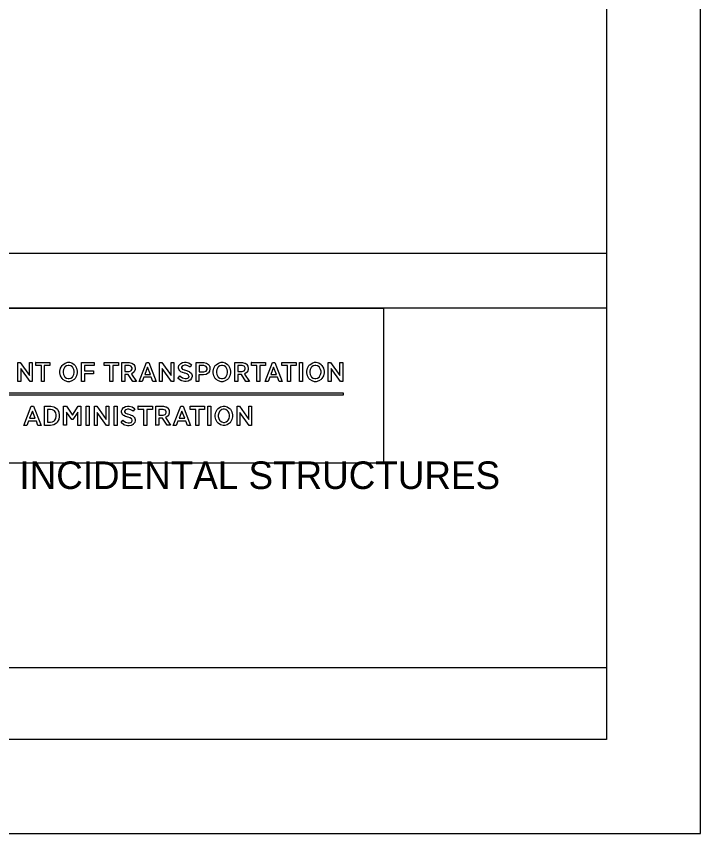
# Model space of a CAD drawing. Extents: x -0.5 to 19.9, y 5.2 to 17.3.
# Drawn here: x 17.634 to 19.938, y 5.667 to 8.417 of the extents above; entities that cross this region are included whole.
import ezdxf

# ---------------------------------------------------------------- set-up
doc = ezdxf.new("R2010")
doc.units = 0
for name, color, linetype in [('BORD-LINE', 7, 'Continuous'), ('MSHA-LOGO', 7, 'Continuous'), ('TTLB-TEXT', 7, 'Continuous'), ('USER-CLIP', 7, 'Continuous'), ('USER-LINE', 7, 'Continuous')]:
    doc.layers.add(name, color=color, linetype=linetype)

msp = doc.modelspace()

# ---------------------------------------------------------------- linework, layer by layer
at = {"layer": 'BORD-LINE'}
for p, q in [((19.6208, 7.6193), (12.2466, 7.6193)), ((19.6208, 7.4352), (15.1479, 7.4352)), ((15.1479, 6.2262), (19.6208, 6.2262))]:
    msp.add_line(p, q, dxfattribs=at)
msp.add_lwpolyline([(12.2466, 16.3375), (19.6208, 16.3375), (19.6208, 5.9844), (12.2466, 5.9844)], close=True, dxfattribs=at)
at = {"layer": 'MSHA-LOGO'}
for points in [[(17.6799, 7.189), (17.6485, 7.2324), (17.6485, 7.189), (17.639, 7.189), (17.639, 7.2525), (17.6465, 7.2525), (17.6779, 7.2091), (17.6779, 7.2525), (17.6874, 7.2525), (17.6874, 7.189)], [(17.6989, 7.2528), (17.747, 7.2528), (17.747, 7.2426), (17.728, 7.2426), (17.728, 7.1893), (17.7182, 7.1893), (17.7182, 7.2426), (17.6992, 7.2426), (17.6992, 7.2528)], [(17.7892, 7.2439), (17.7905, 7.2455), (17.7985, 7.251), (17.8069, 7.2535), (17.8098, 7.2535), (17.8126, 7.2535), (17.821, 7.2512), (17.829, 7.2458), (17.8304, 7.2443), (17.8318, 7.2427), (17.8367, 7.2338), (17.8389, 7.2241), (17.8389, 7.2209), (17.8389, 7.2177), (17.8367, 7.2081), (17.8318, 7.1991), (17.8304, 7.1975), (17.829, 7.196), (17.821, 7.1906), (17.8126, 7.1883), (17.8098, 7.1883), (17.8069, 7.1883), (17.7985, 7.1906), (17.7905, 7.196), (17.7892, 7.1975), (17.7878, 7.1991), (17.7828, 7.208), (17.7807, 7.2177), (17.7807, 7.2209), (17.7807, 7.2241), (17.7828, 7.2335), (17.7878, 7.2424)], [(17.7967, 7.2051), (17.7976, 7.204), (17.8028, 7.2004), (17.8083, 7.1989), (17.8101, 7.1989), (17.8119, 7.1989), (17.8174, 7.2004), (17.8226, 7.204), (17.8235, 7.2051), (17.8244, 7.2061), (17.8276, 7.212), (17.8291, 7.2187), (17.8291, 7.2209), (17.8291, 7.2231), (17.8276, 7.2298), (17.8244, 7.2357), (17.8235, 7.2367), (17.8226, 7.2378), (17.8174, 7.2414), (17.8119, 7.2429), (17.8101, 7.2429), (17.8083, 7.2429), (17.8028, 7.2414), (17.7976, 7.2378), (17.7967, 7.2367), (17.7958, 7.2357), (17.7925, 7.2298), (17.7911, 7.2231), (17.7911, 7.2209), (17.7911, 7.2187), (17.7924, 7.212), (17.7957, 7.2061)], [(17.8536, 7.2528), (17.8955, 7.2528), (17.8955, 7.2426), (17.8634, 7.2426), (17.8634, 7.2245), (17.8932, 7.2245), (17.8932, 7.2143), (17.8634, 7.2143), (17.8634, 7.1893), (17.8536, 7.1893)], [(17.9292, 7.2528), (17.9773, 7.2528), (17.9773, 7.2426), (17.9583, 7.2426), (17.9583, 7.1893), (17.9485, 7.1893), (17.9485, 7.2426), (17.9296, 7.2426), (17.9296, 7.2528)], [(17.9888, 7.189), (17.9888, 7.2525), (18.011, 7.2525), (18.0138, 7.2525), (18.0213, 7.2511), (18.0222, 7.2508), (18.0229, 7.2506), (18.0286, 7.2467), (18.029, 7.2462), (18.0294, 7.2458), (18.0324, 7.2406), (18.0326, 7.24), (18.0329, 7.2394), (18.0336, 7.2342), (18.0336, 7.2324), (18.0336, 7.2295), (18.0309, 7.2217), (18.0303, 7.2209), (18.0298, 7.2201), (18.0222, 7.2143), (18.0212, 7.214), (18.0382, 7.1887), (18.0261, 7.1887), (18.0107, 7.212), (17.9986, 7.212), (17.9986, 7.1887), (17.9888, 7.1887)], [(17.9986, 7.2423), (17.9986, 7.2229), (18.0114, 7.2229), (18.0136, 7.2229), (18.0196, 7.2251), (18.0202, 7.2255), (18.0207, 7.2259), (18.0235, 7.2313), (18.0235, 7.2331), (18.0235, 7.2348), (18.021, 7.2396), (18.0205, 7.24), (18.02, 7.2404), (18.0133, 7.2423), (18.011, 7.2423)], [(18.0719, 7.2528), (18.0794, 7.2528), (18.1043, 7.1893), (18.0938, 7.1893), (18.0883, 7.2035), (18.0627, 7.2035), (18.0572, 7.1893), (18.047, 7.1893)], [(18.0663, 7.2127), (18.085, 7.2127), (18.0755, 7.2367)], [(18.1566, 7.189), (18.1252, 7.2324), (18.1252, 7.189), (18.1157, 7.189), (18.1157, 7.2525), (18.1233, 7.2525), (18.1547, 7.2091), (18.1547, 7.2525), (18.1642, 7.2525), (18.1642, 7.189)], [(18.213, 7.2114), (18.2126, 7.2117), (18.2085, 7.2144), (18.208, 7.2147), (18.2075, 7.2148), (18.2018, 7.2165), (18.2012, 7.2166), (18.2005, 7.2168), (18.1943, 7.2187), (18.1936, 7.2189), (18.193, 7.2192), (18.1872, 7.2219), (18.1868, 7.2222), (18.1863, 7.2226), (18.1822, 7.2269), (18.1819, 7.2275), (18.1815, 7.2281), (18.1799, 7.2338), (18.1799, 7.2357), (18.1799, 7.2374), (18.1814, 7.2426), (18.185, 7.2476), (18.1861, 7.2485), (18.1872, 7.2494), (18.1933, 7.2525), (18.1999, 7.2538), (18.2021, 7.2538), (18.2053, 7.2538), (18.2147, 7.2515), (18.2228, 7.2462), (18.2241, 7.2446), (18.2188, 7.2367), (18.2176, 7.2378), (18.2109, 7.2416), (18.2041, 7.2433), (18.2018, 7.2433), (18.1997, 7.2433), (18.1939, 7.2416), (18.1933, 7.2413), (18.1927, 7.241), (18.19, 7.237), (18.19, 7.2357), (18.19, 7.2345), (18.1922, 7.2311), (18.1926, 7.2308), (18.1931, 7.2305), (18.1985, 7.228), (18.1992, 7.2278), (18.1998, 7.2277), (18.207, 7.2258), (18.2077, 7.2255), (18.2085, 7.2253), (18.2156, 7.2226), (18.2162, 7.2222), (18.2169, 7.2219), (18.2224, 7.2173), (18.2228, 7.2166), (18.2232, 7.216), (18.2254, 7.2095), (18.2254, 7.2074), (18.2254, 7.2055), (18.2239, 7.1999), (18.2202, 7.1948), (18.2192, 7.1939), (18.2181, 7.193), (18.2121, 7.1899), (18.2058, 7.1887), (18.2038, 7.1887), (18.2002, 7.1887), (18.1905, 7.1914), (18.1894, 7.192), (18.1882, 7.1925), (18.1792, 7.1994), (18.1786, 7.2002), (18.1845, 7.2077), (18.1858, 7.2063), (18.1934, 7.2009), (18.2017, 7.1985), (18.2044, 7.1985), (18.2064, 7.1985), (18.2119, 7.2002), (18.2123, 7.2005), (18.2128, 7.2008), (18.2152, 7.2048), (18.2152, 7.2061), (18.2151, 7.2067), (18.2133, 7.211)], [(18.2391, 7.189), (18.2391, 7.2525), (18.262, 7.2525), (18.265, 7.2525), (18.273, 7.2511), (18.2738, 7.2508), (18.2746, 7.2505), (18.2806, 7.2464), (18.281, 7.2459), (18.2814, 7.2454), (18.2845, 7.2399), (18.2846, 7.2393), (18.2848, 7.2388), (18.2856, 7.2335), (18.2856, 7.2318), (18.2856, 7.2299), (18.2845, 7.2248), (18.2843, 7.2242), (18.284, 7.2236), (18.2808, 7.2181), (18.2804, 7.2176), (18.2799, 7.2171), (18.2736, 7.213), (18.2728, 7.2127), (18.272, 7.2124), (18.2643, 7.211), (18.2617, 7.211), (18.2486, 7.211), (18.2486, 7.1893), (18.2391, 7.1893)], [(18.2493, 7.2423), (18.2493, 7.2209), (18.2624, 7.2209), (18.2649, 7.2209), (18.2727, 7.2236), (18.2761, 7.2297), (18.2761, 7.2318), (18.2761, 7.2337), (18.2729, 7.2396), (18.2655, 7.2423), (18.263, 7.2423)], [(18.3052, 7.2439), (18.3066, 7.2455), (18.3146, 7.251), (18.323, 7.2535), (18.3259, 7.2535), (18.3287, 7.2535), (18.3371, 7.2512), (18.3451, 7.2458), (18.3465, 7.2443), (18.3478, 7.2427), (18.3528, 7.2338), (18.355, 7.2241), (18.355, 7.2209), (18.355, 7.2177), (18.3528, 7.2081), (18.3478, 7.1991), (18.3465, 7.1975), (18.3451, 7.196), (18.3371, 7.1906), (18.3287, 7.1883), (18.3259, 7.1883), (18.323, 7.1883), (18.3146, 7.1906), (18.3066, 7.196), (18.3052, 7.1975), (18.3038, 7.1991), (18.2989, 7.208), (18.2967, 7.2177), (18.2967, 7.2209), (18.2968, 7.2232), (18.299, 7.2335), (18.3038, 7.2424)], [(18.3128, 7.2051), (18.3136, 7.204), (18.3188, 7.2004), (18.3243, 7.1989), (18.3262, 7.1989), (18.328, 7.1989), (18.3335, 7.2004), (18.3387, 7.204), (18.3396, 7.2051), (18.3405, 7.2061), (18.3437, 7.212), (18.3452, 7.2187), (18.3452, 7.2209), (18.3452, 7.2231), (18.3437, 7.2298), (18.3405, 7.2357), (18.3396, 7.2367), (18.3387, 7.2378), (18.3335, 7.2414), (18.328, 7.2429), (18.3262, 7.2429), (18.3244, 7.2429), (18.319, 7.2414), (18.3137, 7.2378), (18.3128, 7.2367), (18.3119, 7.2357), (18.3086, 7.2298), (18.3072, 7.2231), (18.3072, 7.2209), (18.3072, 7.2187), (18.3085, 7.212), (18.3118, 7.2061)], [(18.3697, 7.189), (18.3697, 7.2525), (18.3919, 7.2525), (18.3947, 7.2525), (18.4023, 7.2511), (18.4031, 7.2508), (18.4038, 7.2506), (18.4095, 7.2467), (18.4099, 7.2462), (18.4104, 7.2458), (18.4133, 7.2406), (18.4135, 7.24), (18.4137, 7.2394), (18.4145, 7.2342), (18.4145, 7.2324), (18.4145, 7.2295), (18.4118, 7.2217), (18.4113, 7.2209), (18.4107, 7.2201), (18.4031, 7.2143), (18.4021, 7.214), (18.4191, 7.1887), (18.407, 7.1887), (18.3916, 7.212), (18.3795, 7.212), (18.3795, 7.1887), (18.3697, 7.1887)], [(18.3795, 7.2423), (18.3795, 7.2229), (18.3923, 7.2229), (18.3945, 7.2229), (18.4005, 7.2251), (18.4011, 7.2255), (18.4016, 7.2259), (18.4044, 7.2313), (18.4044, 7.2331), (18.4044, 7.2348), (18.4019, 7.2396), (18.4014, 7.24), (18.4009, 7.2404), (18.3942, 7.2423), (18.3919, 7.2423)], [(18.4247, 7.2528), (18.4728, 7.2528), (18.4728, 7.2426), (18.4538, 7.2426), (18.4538, 7.1893), (18.444, 7.1893), (18.444, 7.2426), (18.425, 7.2426), (18.425, 7.2528)], [(18.4967, 7.2528), (18.5042, 7.2528), (18.5291, 7.1893), (18.5186, 7.1893), (18.513, 7.2035), (18.4872, 7.2035), (18.4816, 7.1893), (18.4718, 7.1893)], [(18.4908, 7.2127), (18.5094, 7.2127), (18.4999, 7.2367)], [(18.5278, 7.2528), (18.5759, 7.2528), (18.5759, 7.2426), (18.5569, 7.2426), (18.5569, 7.1893), (18.5471, 7.1893), (18.5471, 7.2426), (18.5281, 7.2426), (18.5281, 7.2528)], [(18.5873, 7.2528), (18.5971, 7.2528), (18.5971, 7.1893), (18.5873, 7.1893)], [(18.6201, 7.2439), (18.6214, 7.2455), (18.6294, 7.251), (18.6378, 7.2535), (18.6407, 7.2535), (18.6435, 7.2535), (18.6519, 7.2512), (18.6599, 7.2458), (18.6613, 7.2443), (18.6627, 7.2427), (18.6676, 7.2338), (18.6698, 7.2241), (18.6698, 7.2209), (18.6698, 7.2177), (18.6676, 7.2081), (18.6627, 7.1991), (18.6613, 7.1975), (18.6599, 7.196), (18.6519, 7.1906), (18.6435, 7.1883), (18.6407, 7.1883), (18.6378, 7.1883), (18.6294, 7.1906), (18.6214, 7.196), (18.6201, 7.1975), (18.6187, 7.1991), (18.6137, 7.208), (18.6115, 7.2177), (18.6115, 7.2209), (18.6115, 7.2241), (18.6136, 7.2335), (18.6186, 7.2424)], [(18.6272, 7.2051), (18.6281, 7.204), (18.6333, 7.2004), (18.6388, 7.1989), (18.6407, 7.1989), (18.6425, 7.1989), (18.648, 7.2004), (18.6532, 7.204), (18.6541, 7.2051), (18.655, 7.2061), (18.6582, 7.212), (18.6596, 7.2187), (18.6596, 7.2209), (18.6596, 7.2231), (18.6582, 7.2298), (18.655, 7.2357), (18.6541, 7.2367), (18.6532, 7.2378), (18.648, 7.2414), (18.6425, 7.2429), (18.6407, 7.2429), (18.6389, 7.2429), (18.6335, 7.2414), (18.6282, 7.2378), (18.6272, 7.2367), (18.6263, 7.2357), (18.6231, 7.2298), (18.6217, 7.2231), (18.6217, 7.2209), (18.6217, 7.2187), (18.6231, 7.212), (18.6263, 7.2061)], [(18.7251, 7.189), (18.6937, 7.2324), (18.6937, 7.189), (18.6842, 7.189), (18.6842, 7.2525), (18.6917, 7.2525), (18.7231, 7.2091), (18.7231, 7.2525), (18.7326, 7.2525), (18.7326, 7.189)], [(16.617, 7.151), (18.7337, 7.151), (18.7337, 7.1432), (16.617, 7.1432)], [(17.6843, 7.1055), (17.6919, 7.1055), (17.7172, 7.0413), (17.7066, 7.0413), (17.7012, 7.0554), (17.675, 7.0554), (17.6696, 7.0413), (17.6593, 7.0413)], [(17.7284, 7.1055), (17.7462, 7.1055), (17.75, 7.1055), (17.7602, 7.1033), (17.7613, 7.1029), (17.7623, 7.1025), (17.7708, 7.0967), (17.7715, 7.0959), (17.7721, 7.0951), (17.7766, 7.0869), (17.7769, 7.0859), (17.7772, 7.085), (17.7785, 7.0768), (17.7785, 7.074), (17.7785, 7.0707), (17.7764, 7.0608), (17.7716, 7.0518), (17.7702, 7.0503), (17.7688, 7.0488), (17.7598, 7.0435), (17.7489, 7.0413), (17.7453, 7.0413), (17.7284, 7.0413)], [(17.7932, 7.1055), (17.8022, 7.1055), (17.8226, 7.0756), (17.8424, 7.1055), (17.8511, 7.1055), (17.8511, 7.0413), (17.8411, 7.0413), (17.8411, 7.0859), (17.8236, 7.0605), (17.821, 7.0605), (17.8031, 7.0862), (17.8031, 7.0416), (17.7932, 7.0416)], [(17.8689, 7.1055), (17.8788, 7.1055), (17.8788, 7.0413), (17.8689, 7.0413)], [(17.9379, 7.0413), (17.9063, 7.085), (17.9063, 7.0413), (17.8967, 7.0413), (17.8967, 7.1055), (17.9044, 7.1055), (17.936, 7.0615), (17.936, 7.1055), (17.9456, 7.1055), (17.9456, 7.0413)], [(17.9632, 7.1055), (17.9731, 7.1055), (17.9731, 7.0413), (17.9632, 7.0413)], [(18.022, 7.0634), (18.0217, 7.0638), (18.0174, 7.0664), (18.0169, 7.0667), (18.0163, 7.0668), (18.0105, 7.0688), (18.0098, 7.0689), (18.0092, 7.0691), (18.0028, 7.0709), (18.0022, 7.0711), (18.0015, 7.0714), (17.9957, 7.074), (17.9951, 7.0744), (17.9946, 7.0747), (17.9904, 7.0793), (17.99, 7.0798), (17.9897, 7.0804), (17.9881, 7.0862), (17.9881, 7.0882), (17.9881, 7.0899), (17.9898, 7.0952), (17.9935, 7.1001), (17.9945, 7.101), (17.9955, 7.1019), (18.0017, 7.1049), (18.0085, 7.1062), (18.0108, 7.1062), (18.014, 7.1062), (18.0235, 7.1038), (18.0318, 7.0984), (18.0332, 7.0968), (18.0277, 7.0888), (18.0265, 7.0899), (18.0198, 7.0939), (18.0128, 7.0956), (18.0105, 7.0956), (18.0083, 7.0956), (18.0024, 7.094), (18.0019, 7.0936), (18.0013, 7.0933), (17.9983, 7.0892), (17.9983, 7.0878), (17.9983, 7.0866), (18.0005, 7.0831), (18.0009, 7.0827), (18.0013, 7.0824), (18.0069, 7.08), (18.0076, 7.0798), (18.0083, 7.0797), (18.0154, 7.0775), (18.0162, 7.0773), (18.017, 7.077), (18.0242, 7.0743), (18.0249, 7.074), (18.0255, 7.0737), (18.0311, 7.0689), (18.0316, 7.0683), (18.032, 7.0676), (18.0341, 7.0611), (18.0341, 7.0589), (18.0341, 7.0571), (18.0325, 7.0513), (18.0288, 7.046), (18.0277, 7.0451), (18.0267, 7.0443), (18.0206, 7.0411), (18.0142, 7.0397), (18.0121, 7.0397), (18.0084, 7.0397), (17.9986, 7.0423), (17.9974, 7.0429), (17.9962, 7.0435), (17.9872, 7.0504), (17.9865, 7.0512), (17.9926, 7.0589), (17.9939, 7.0574), (18.0015, 7.052), (18.0101, 7.0496), (18.013, 7.0496), (18.015, 7.0496), (18.0205, 7.0512), (18.021, 7.0516), (18.0215, 7.0519), (18.0239, 7.056), (18.0239, 7.0573), (18.0239, 7.0589), (18.0223, 7.0631)], [(18.0434, 7.1055), (18.092, 7.1055), (18.092, 7.0949), (18.0728, 7.0949), (18.0728, 7.0413), (18.0629, 7.0413), (18.0629, 7.0949), (18.0437, 7.0949), (18.0437, 7.1055)], [(18.1035, 7.0413), (18.1035, 7.1055), (18.1261, 7.1055), (18.1289, 7.1055), (18.1365, 7.1041), (18.1373, 7.1039), (18.1381, 7.1037), (18.144, 7.0999), (18.1444, 7.0994), (18.1448, 7.0989), (18.1477, 7.0936), (18.1479, 7.093), (18.148, 7.0924), (18.1488, 7.0873), (18.1488, 7.0856), (18.1488, 7.0827), (18.1459, 7.0748), (18.1453, 7.074), (18.1447, 7.0732), (18.137, 7.0676), (18.136, 7.0673), (18.1533, 7.0416), (18.1412, 7.0416), (18.1255, 7.065), (18.1134, 7.065), (18.1134, 7.0416), (18.1035, 7.0416)], [(18.1875, 7.1055), (18.1952, 7.1055), (18.2204, 7.0413), (18.2099, 7.0413), (18.2041, 7.0554), (18.1779, 7.0554), (18.1725, 7.0413), (18.1623, 7.0413)], [(18.2188, 7.1055), (18.2674, 7.1055), (18.2674, 7.0949), (18.2482, 7.0949), (18.2482, 7.0413), (18.2383, 7.0413), (18.2383, 7.0949), (18.2191, 7.0949), (18.2191, 7.1055)], [(18.2789, 7.1055), (18.2888, 7.1055), (18.2888, 7.0413), (18.2789, 7.0413)], [(18.3118, 7.0965), (18.3132, 7.0981), (18.3213, 7.1037), (18.3297, 7.1062), (18.3325, 7.1062), (18.3354, 7.1062), (18.3439, 7.1038), (18.3519, 7.0984), (18.3533, 7.0968), (18.3547, 7.0953), (18.3597, 7.0863), (18.362, 7.0766), (18.362, 7.0734), (18.362, 7.0702), (18.3598, 7.0606), (18.3547, 7.0516), (18.3533, 7.05), (18.3519, 7.0484), (18.3438, 7.0429), (18.3353, 7.0406), (18.3325, 7.0406), (18.3297, 7.0406), (18.3211, 7.043), (18.3131, 7.0484), (18.3118, 7.05), (18.3103, 7.0515), (18.3053, 7.0605), (18.3032, 7.0702), (18.3032, 7.0734), (18.3032, 7.0766), (18.3053, 7.0861), (18.3103, 7.095)], [(18.3191, 7.0573), (18.3201, 7.0563), (18.3254, 7.0527), (18.3308, 7.0512), (18.3325, 7.0512), (18.3344, 7.0512), (18.34, 7.0527), (18.3453, 7.0563), (18.3463, 7.0573), (18.3472, 7.0584), (18.3504, 7.0644), (18.3517, 7.0711), (18.3517, 7.0734), (18.3517, 7.0756), (18.3503, 7.0823), (18.3469, 7.0884), (18.346, 7.0894), (18.345, 7.0905), (18.3397, 7.0941), (18.3343, 7.0956), (18.3325, 7.0956), (18.3307, 7.0956), (18.3252, 7.0941), (18.32, 7.0905), (18.3191, 7.0894), (18.3183, 7.0884), (18.3151, 7.0824), (18.3137, 7.0756), (18.3137, 7.0734), (18.3137, 7.0711), (18.3151, 7.0644), (18.3183, 7.0584)], [(18.4182, 7.0413), (18.3865, 7.085), (18.3865, 7.0413), (18.377, 7.0413), (18.377, 7.1055), (18.3846, 7.1055), (18.4163, 7.0615), (18.4163, 7.1055), (18.4259, 7.1055), (18.4259, 7.0413)], [(17.6785, 7.065), (17.6974, 7.065), (17.6878, 7.0894)], [(17.7383, 7.0949), (17.7383, 7.0516), (17.7459, 7.0516), (17.7484, 7.0516), (17.7558, 7.0531), (17.7619, 7.0566), (17.7629, 7.0577), (17.7638, 7.0587), (17.767, 7.0649), (17.7683, 7.0718), (17.7683, 7.074), (17.7683, 7.0763), (17.7669, 7.0831), (17.7628, 7.0897), (17.7559, 7.0936), (17.7486, 7.0949), (17.7462, 7.0949)], [(18.1134, 7.0949), (18.1134, 7.0753), (18.1261, 7.0753), (18.1284, 7.0753), (18.1345, 7.0775), (18.1351, 7.0779), (18.1356, 7.0784), (18.1383, 7.0836), (18.1383, 7.0853), (18.1383, 7.0871), (18.1359, 7.0919), (18.1354, 7.0923), (18.1349, 7.0927), (18.1281, 7.0949), (18.1258, 7.0949)], [(18.1817, 7.065), (18.2006, 7.065), (18.191, 7.0894)]]:
    msp.add_lwpolyline(points, close=True, dxfattribs=at)
at = {"layer": 'USER-CLIP'}
msp.add_lwpolyline([(19.9377, 16.6675), (11.4377, 16.6675), (11.4377, 5.6675), (19.9377, 5.6675)], close=True, dxfattribs=at)
at = {"layer": 'USER-LINE'}
msp.add_lwpolyline([(18.8699, 6.9145), (15.8988, 6.9145), (15.8988, 7.4352), (18.8699, 7.4352)], close=True, dxfattribs=at)

# ---------------------------------------------------------------- texts
at = {"layer": 'BORD-LINE'}
msp.add_text('HDVBARREIRA', height=6e-12, rotation=180, dxfattribs=at).set_placement((19.6208, 7.4352))
at = {"layer": 'TTLB-TEXT'}
msp.add_text('STANDARDS FOR HIGHWAYS AND INCIDENTAL STRUCTURES', height=0.09269, dxfattribs=at).set_placement((15.5437, 6.8272))

doc.saveas('drawing.dxf')
